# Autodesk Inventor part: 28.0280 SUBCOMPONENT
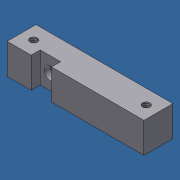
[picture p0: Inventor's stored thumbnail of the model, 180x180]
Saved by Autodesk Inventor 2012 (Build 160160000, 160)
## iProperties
Created: 2007-06
Part Number: 28.0280 SUBCOMPONENT
Material: Aluminum-6061
Document SubType Name: Modeling
Designer: Andy Moles
Density: 2.71 g/cm^3
Mass: 84.809 g
Surface Area: 86.2417 cm^2
Volume: 31.2948 cm^3
Stock Number: SLIDE CLAMPING AL BLOCK FOR SLIDE LWN-S
Author: Andy Moles
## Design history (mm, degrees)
sketch "Sketch1"
  geometry: L1 (-29.25, -3.5)-(-29.25, -9.5); L2 (-29.25, -9.5)-(-45, -9.5); L3 (-45, -9.5)-(-45, 9.5); L4 (-45, 9.5)-(45, 9.5); L5 (45, 9.5)-(45, -9.5); L6 (45, -9.5)-(-15.75, -9.5); L7 (-15.75, -9.5)-(-15.75, -3.5); L8 (-45, 0)-(-49.68, 0); L9 (-29.25, -3.5)-(-15.75, -3.5); L10 (-22.5, -3.5)-(-22.5, 2.838); 3 further points
  constraints: 20 end point, 4 parallel, 3 horizontal, 3 midpoint, 2 horizontal alignment, 2 perpendicular, 1 vertical, 1 vertical alignment
  dimensions: "d0" = 19 distance of L2.end L3.end; "d1" = 90 distance of L3.end L4.end; "d2" = 6 distance of L6.end L7.end; "d3" = 13.5 distance of L7.end L1.start; "d5" = 0 distance from line of L8 point (0, 0); "d26" = 22.5 distance from line of point (0, 0) L10
extrude "Extrusion1" new body sketch "Sketch1" distance "d8" = 20; taper "d9" = 0 deg
sketch "Sketch2"
  geometry: 3 further points
  constraints: 2 horizontal alignment
  dimensions: "d27" = 74 distance of point (37, 0) point (-37, 0); "d28" = 37 distance of point (37, 0) point (0, 0) (= 0.5 x d27)
hole "Hole3" sketch "Sketch2" at (-37, 0), (37, 0) diameter "d29" = 4.917; stored, may be unused: countersink angle "d33" = 90 deg, drill point angle "d35" = 118 deg; dims "d30" = 6, "d31" = 4, "d32" = 2, "d34" = 8
sketch "Sketch3"
  geometry: L1 (0, 0)-(13.5, 0) reference; L2 (0, 0)-(0, -20) reference; C1 r 3.25 at (6.75, -10); 3 further points
  constraints: 2 midpoint, 1 centre point, 1 horizontal alignment, 1 vertical alignment
  dimensions: "d36" = 6.5 diameter of C1
extrude "Extrusion2" cut sketch "Sketch3" stored distance "d37" = 10; taper "d38" = 0 deg
hole "Hole4" diameter "d41" = 8.5; stored, may be unused: countersink angle "d45" = 90 deg, drill point angle "d47" = 0 deg; dims "d39" = 10, "d40" = 10, "d42" = 6, "d43" = 4, "d44" = 2, "d46" = 4
body "Solid1"
